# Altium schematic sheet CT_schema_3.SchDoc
size 214 x 189 mm
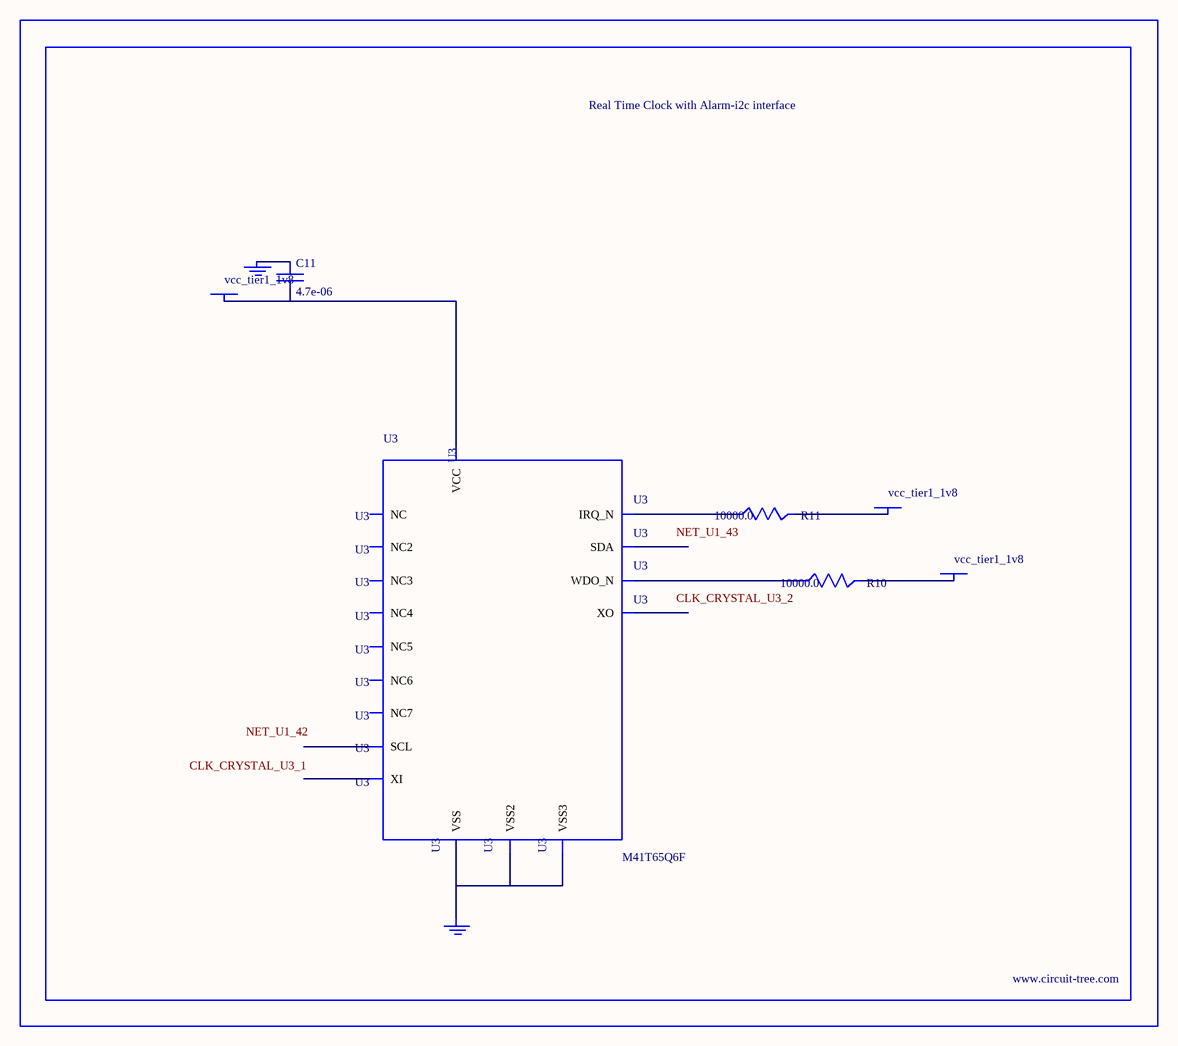
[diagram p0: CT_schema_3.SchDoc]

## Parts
BORDER2  (no value)
C11  4.7e-06  [C0805]
GND_INSTANCE_2_0  (no value)
GND_INSTANCE_2_1  (no value)
POWER_INSTANCE_2_0  vcc_tier1_1v8
POWER_INSTANCE_2_1  vcc_tier1_1v8
POWER_INSTANCE_2_2  vcc_tier1_1v8
R10  10000.0  [R0603]
R11  10000.0  [R0603]
U3  M41T65Q6F  [M41T65_QFN-16]

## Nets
NetC11_1: C11.1 GND_INSTANCE_2_0.0(GND)
NetC11_2: C11.2 POWER_INSTANCE_2_2.0(PWR) U3.14(VCC)
NetGND_INSTANCE_2_1_0: GND_INSTANCE_2_1.0(GND) U3.3(VSS) U3.5(VSS2) U3.17(VSS3)
NetPOWER_INSTANCE_2_0_0: POWER_INSTANCE_2_0.0(PWR) R10.2
NetPOWER_INSTANCE_2_1_0: POWER_INSTANCE_2_1.0(PWR) R11.2
NetR10_1: R10.1 U3.4(WDO_N)
NetR11_1: R11.1 U3.11(IRQ_N)

Not connected (* = marked no-connect by the designer): U3 1(XI) 2(XO) 6(NC) 7(NC2) 8(NC3) 9(SDA) 10(SCL) 12(NC4) 13(NC5) 15(NC6) 16(NC7)

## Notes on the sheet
- Labels drawn without touching a wire or pin: CLK_CRYSTAL_U3_1, CLK_CRYSTAL_U3_2, NET_U1_42, NET_U1_43

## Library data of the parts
BORDER2 = BORDER_PAGE2
C11 = C0805C475K4RACTU
GND_INSTANCE_2_0 GND_INSTANCE_2_1 = GND
POWER_INSTANCE_2_0-POWER_INSTANCE_2_2 = PWR
R10 R11 = RC0603JR-0710KL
